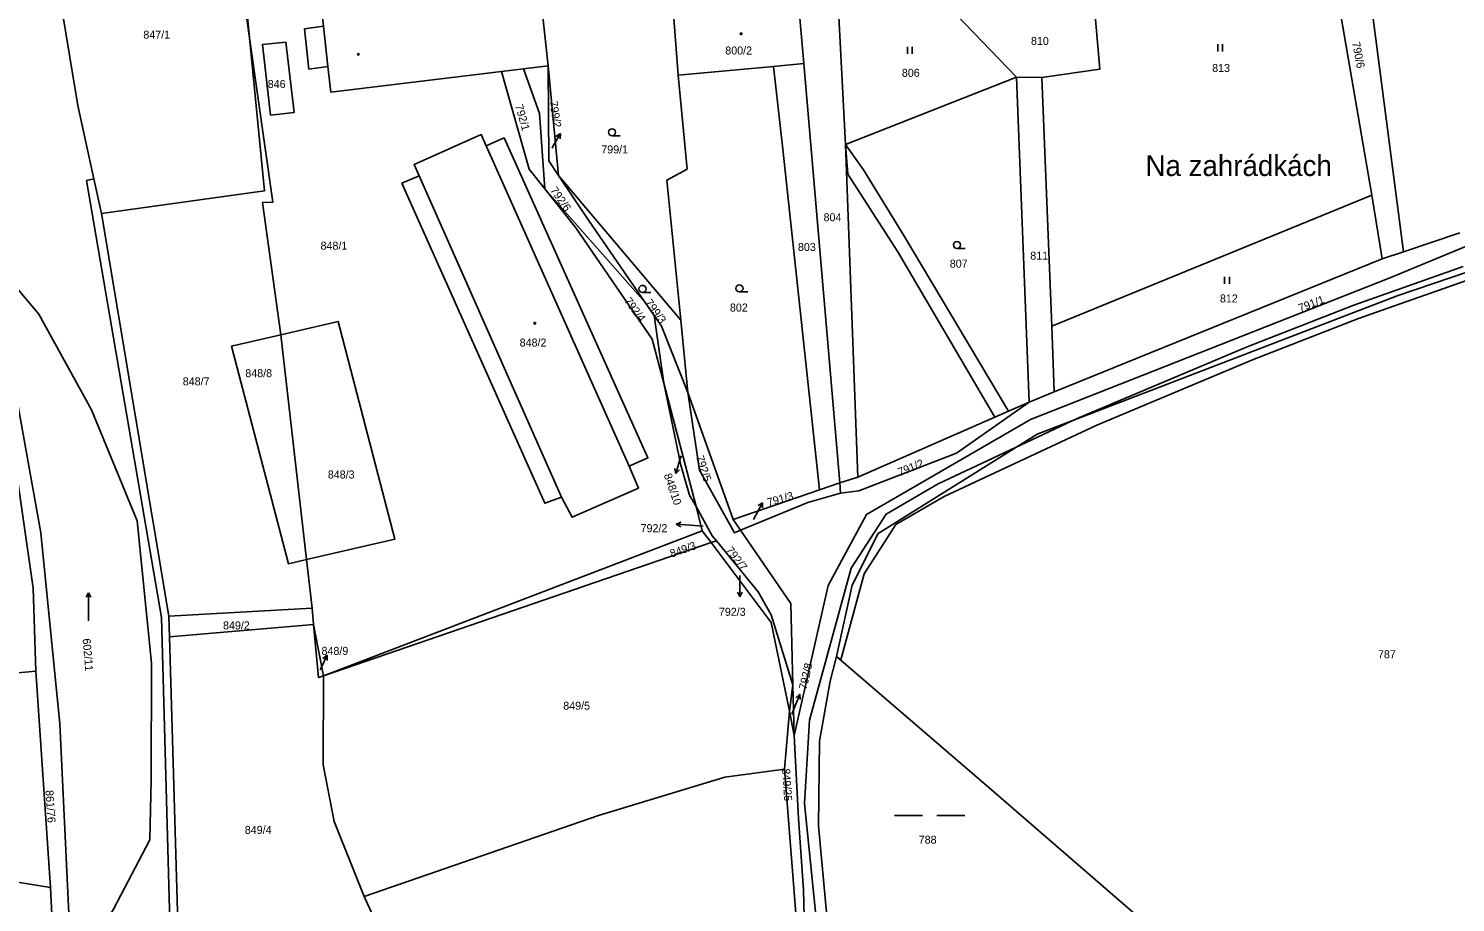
# Model space of a CAD drawing. Extents: x -757266 to -753360, y -1162585 to -1157740.
# Drawn here: x -756892.7 to -756589.6, y -1159563.7 to -1159378.1 of the extents above; entities that cross this region are included whole.
import ezdxf

# ---------------------------------------------------------------- set-up
doc = ezdxf.new("R2010")
doc.units = 0
for name, color, linetype in [('Hranice parcel', 7, 'Continuous'), ('Parcelní čísla', 7, 'Continuous'), ('Pop  PČ popisy', 7, 'Continuous'), ('Vnitřní kresba', 7, 'Continuous'), ('Věcná břemena k části', 7, 'Continuous'), ('Značky budov', 7, 'Continuous'), ('Značky kultur', 7, 'Continuous')]:
    doc.layers.add(name, color=color, linetype=linetype)

msp = doc.modelspace()

# ---------------------------------------------------------------- linework, layer by layer
at = {"layer": 'Hranice parcel'}
for p, q in [((-756719.18, -1159402.74), (-756720.72, -1159372.88)), ((-756682.81, -1159388.39), (-756699.51, -1159371.08)), ((-756782.33, -1159386), (-756783.53, -1159374.95)), ((-756734.47, -1159386.15), (-756727.97, -1159385.55)), ((-756720.33, -1159474.57), (-756727.97, -1159385.55)), ((-756792.21, -1159387.19), (-756787.55, -1159386.63)), ((-756787.55, -1159386.63), (-756782.33, -1159386)), ((-756782.33, -1159386), (-756780.14, -1159409.28)), ((-756754.68, -1159388), (-756734.47, -1159386.15)), ((-756719.18, -1159402.74), (-756682.81, -1159388.39)), ((-756680.1, -1159457.44), (-756682.81, -1159388.39)), ((-756682.81, -1159388.39), (-756677.42, -1159388.52)), ((-756675.34, -1159441.31), (-756677.42, -1159388.52)), ((-756716.5, -1159473.39), (-756719.18, -1159402.74)), ((-756780.14, -1159409.28), (-756754.16, -1159440.02)), ((-756877.23, -1159417.39), (-756878.84, -1159410.04)), ((-756761.71, -1159436.3), (-756783.04, -1159412.14)), ((-756607.32, -1159413.48), (-756675.34, -1159441.31)), ((-756605.14, -1159427.02), (-756607.32, -1159413.48)), ((-756862.88, -1159502.93), (-756877.23, -1159417.39)), ((-756600.59, -1159425.5), (-756588.6, -1159421.48)), ((-756674.79, -1159455.28), (-756605.14, -1159427.02)), ((-756605.14, -1159427.02), (-756600.59, -1159425.5)), ((-756759.8, -1159439.07), (-756761.71, -1159436.3)), ((-756757.74, -1159453.43), (-756759.8, -1159439.07)), ((-756754.16, -1159440.02), (-756752.65, -1159455.42)), ((-756839.14, -1159443.12), (-756833.66, -1159490.89)), ((-756674.79, -1159455.28), (-756675.34, -1159441.31)), ((-756757.74, -1159453.43), (-756750.9, -1159479.64)), ((-756752.65, -1159455.42), (-756743.03, -1159482.35)), ((-756680.1, -1159457.44), (-756674.79, -1159455.28)), ((-756720.33, -1159474.57), (-756716.5, -1159473.39)), ((-756743.03, -1159482.35), (-756724.65, -1159476.05)), ((-756724.65, -1159476.05), (-756720.33, -1159474.57)), ((-756720.33, -1159474.57), (-756720.2, -1159476.81)), ((-756749.57, -1159484.76), (-756750.9, -1159479.64)), ((-756743.03, -1159482.35), (-756741.45, -1159484.66)), ((-756749.57, -1159484.76), (-756830.03, -1159515.56)), ((-756747.67, -1159487.28), (-756749.57, -1159484.76)), ((-756830.03, -1159515.56), (-756747.67, -1159487.28)), ((-756747.67, -1159487.28), (-756746.55, -1159486.9)), ((-756833.66, -1159490.89), (-756832.47, -1159501.24)), ((-756832.47, -1159501.24), (-756862.88, -1159502.93)), ((-756862.76, -1159507.3), (-756862.88, -1159502.93)), ((-756832.14, -1159504.69), (-756832.47, -1159501.24)), ((-756862.76, -1159507.3), (-756832.14, -1159504.69)), ((-756830.03, -1159515.56), (-756832.14, -1159504.69)), ((-756860.32, -1159592.53), (-756862.76, -1159507.3)), ((-756909.6, -1159516.31), (-756891.18, -1159514.56)), ((-756888.08, -1159560.56), (-756891.18, -1159514.56)), ((-756730.32, -1159517.52), (-756731.05, -1159523.12)), ((-756730.02, -1159528.29), (-756730.32, -1159517.52)), ((-756732.09, -1159535.43), (-756731.05, -1159523.12)), ((-756731.05, -1159523.12), (-756730.02, -1159528.29)), ((-756728.56, -1159581), (-756732.09, -1159535.43)), ((-756924.26, -1159554.77), (-756888.08, -1159560.56)), ((-756886.84, -1159585.24), (-756888.08, -1159560.56)), ((-756809.73, -1159588.01), (-756821.38, -1159562.46))]:
    msp.add_line(p, q, dxfattribs=at)
for points in [[(-756836.08, -1159324.04), (-756834.39, -1159339.05), (-756830.04, -1159377.58), (-756829.16, -1159386.14), (-756828.46, -1159391.58), (-756792.21, -1159387.19)], [(-756617.96, -1159329.16), (-756613.19, -1159328.59), (-756600.59, -1159425.5)], [(-756607.32, -1159413.48), (-756614.2, -1159373.6), (-756617.96, -1159329.16)], [(-756882.88, -1159333.6), (-756868.52, -1159332.73), (-756848.31, -1159353.74), (-756845.75, -1159380.05)], [(-756845.75, -1159380.05), (-756849.31, -1159354.8), (-756871.83, -1159335.95), (-756891.14, -1159340.49)], [(-756878.84, -1159410.04), (-756882.25, -1159394.41), (-756891.14, -1159340.49)], [(-756755.93, -1159368.82), (-756755.45, -1159375.88), (-756755.64, -1159375.9), (-756754.68, -1159388)], [(-756677.42, -1159388.52), (-756665.13, -1159386.75), (-756666.76, -1159367.95)], [(-756727.97, -1159385.55), (-756729.06, -1159373.5), (-756728.59, -1159373.55)], [(-756877.23, -1159417.39), (-756842.59, -1159412.57), (-756845.75, -1159380.05)], [(-756845.75, -1159380.05), (-756840.83, -1159414.98), (-756843.03, -1159415.06), (-756839.14, -1159443.12)], [(-756838.02, -1159381), (-756842.99, -1159381.48), (-756841.28, -1159396.49), (-756836.3, -1159395.96), (-756838.02, -1159381)], [(-756783.04, -1159412.14), (-756786.33, -1159407.98), (-756792.21, -1159387.19)], [(-756783.04, -1159412.14), (-756784.18, -1159396.16), (-756787.55, -1159386.63)], [(-756782.33, -1159386), (-756782.19, -1159406.22), (-756780.14, -1159409.28)], [(-756754.68, -1159388), (-756752.8, -1159407.95), (-756757.07, -1159410.29), (-756754.16, -1159440.02)], [(-756724.65, -1159476.05), (-756732.47, -1159403.74), (-756734.47, -1159386.15)], [(-756813.44, -1159410.94), (-756782.99, -1159478.91), (-756779.46, -1159477.67), (-756777.21, -1159481.9), (-756763.13, -1159475.73), (-756765.12, -1159471.06), (-756761.14, -1159469.29), (-756791.66, -1159401.32), (-756795.5, -1159403.03), (-756796.58, -1159400.61), (-756810.8, -1159406.95), (-756809.73, -1159409.36), (-756813.44, -1159410.94)], [(-756518.53, -1159405.91), (-756566.06, -1159415.52), (-756603.63, -1159431.14), (-756679.86, -1159461.14), (-756714.68, -1159481.31), (-756722.84, -1159496.4), (-756730.02, -1159528.29)], [(-756780.14, -1159409.28), (-756773.63, -1159418.99), (-756761.71, -1159436.3)], [(-756878.84, -1159410.04), (-756880.4, -1159410.39), (-756864.45, -1159503.19), (-756861.05, -1159627.24), (-756861.08, -1159653.69), (-756855.08, -1159693.86), (-756853.1, -1159698.91)], [(-756783.04, -1159412.14), (-756776.47, -1159420.45), (-756760.19, -1159444.04), (-756757.74, -1159453.43)], [(-756528.91, -1159414.06), (-756563.38, -1159421.74), (-756601.97, -1159434.88), (-756678.44, -1159464.24), (-756712.18, -1159485.32), (-756717.75, -1159496.31), (-756721.03, -1159511.46)], [(-756900.5, -1159427.51), (-756898.83, -1159429.01), (-756890.5, -1159438.79), (-756879.34, -1159459.1), (-756869.66, -1159482.64), (-756866.57, -1159512.91), (-756866.68, -1159537.66), (-756866.93, -1159550.4), (-756874.67, -1159565.14), (-756883.49, -1159579.55)], [(-756900.5, -1159427.51), (-756890.08, -1159485.19), (-756886.05, -1159525.8), (-756883.49, -1159579.55)], [(-756759.8, -1159439.07), (-756758.26, -1159441.32), (-756752.65, -1159455.42)], [(-756839.14, -1159443.12), (-756849.57, -1159445.53), (-756837.5, -1159491.78), (-756833.66, -1159490.89)], [(-756833.66, -1159490.89), (-756814.88, -1159486.56), (-756826.95, -1159440.31), (-756839.14, -1159443.12)], [(-756750.9, -1159479.64), (-756752.26, -1159477.19), (-756754.16, -1159470.84), (-756757.74, -1159453.43)], [(-756752.65, -1159455.42), (-756750.17, -1159471.92), (-756742.74, -1159485.19), (-756741.45, -1159484.66)], [(-756680.1, -1159457.44), (-756695.58, -1159468.27), (-756716.3, -1159476.28), (-756720.2, -1159476.81)], [(-756716.5, -1159473.39), (-756687.42, -1159460.65), (-756684.49, -1159459.36), (-756680.1, -1159457.44)], [(-756891.18, -1159514.56), (-756891.71, -1159496.94), (-756896.42, -1159464.4)], [(-756746.55, -1159486.9), (-756747.47, -1159485.86), (-756750.9, -1159479.64)], [(-756720.2, -1159476.81), (-756727.15, -1159478.74), (-756741.45, -1159484.66)], [(-756741.45, -1159484.66), (-756730.79, -1159500.23), (-756730.32, -1159517.52)], [(-756747.67, -1159487.28), (-756734.93, -1159504.24), (-756731.05, -1159523.12)], [(-756730.32, -1159517.52), (-756734.97, -1159502.66), (-756737.73, -1159497.74), (-756746.55, -1159486.9)], [(-756832.14, -1159504.69), (-756831.08, -1159515.96), (-756830.03, -1159515.56)], [(-756721.03, -1159511.46), (-756722.4, -1159516.74), (-756724.7, -1159529.43), (-756724.87, -1159547.42), (-756723.02, -1159567.31)], [(-756721.03, -1159511.46), (-756688.71, -1159539.34), (-756653.94, -1159569.39), (-756651.67, -1159571.35)], [(-756821.38, -1159562.46), (-756827.77, -1159546.53), (-756830.12, -1159534.52), (-756830.03, -1159515.56)], [(-756730.02, -1159528.29), (-756729.15, -1159545.86), (-756728.07, -1159561.05), (-756727.24, -1159595.66), (-756727.85, -1159612.75), (-756728.58, -1159632.24), (-756729.69, -1159654.04)], [(-756821.38, -1159562.46), (-756771.64, -1159545.22), (-756744.75, -1159537.13), (-756732.09, -1159535.43)]]:
    msp.add_lwpolyline(points, dxfattribs=at)
at = {"layer": 'Pop  PČ popisy'}
for p, q in [((-756781.22, -1159403), (-756779.72, -1159400.401)), ((-756779.72, -1159400.401), (-756780.654, -1159401.018)), ((-756779.72, -1159400.401), (-756779.787, -1159401.519)), ((-756781.5, -1159403.49), (-756781.22, -1159403)), ((-756754.34, -1159469.74), (-756755.167, -1159472.625)), ((-756754.08, -1159468.87), (-756754.34, -1159469.74)), ((-756755.167, -1159472.625), (-756755.372, -1159471.524)), ((-756755.167, -1159472.625), (-756754.41, -1159471.8)), ((-756738.21, -1159481.43), (-756736.755, -1159478.805)), ((-756736.755, -1159478.805), (-756737.679, -1159479.438)), ((-756736.755, -1159478.805), (-756736.803, -1159479.924)), ((-756738.72, -1159482.36), (-756738.21, -1159481.43)), ((-756755.104, -1159483.361), (-756754.07, -1159482.931)), ((-756752.11, -1159483.57), (-756755.104, -1159483.361)), ((-756755.104, -1159483.361), (-756754.14, -1159483.93)), ((-756749.36, -1159483.78), (-756752.11, -1159483.57)), ((-756741.61, -1159494.29), (-756741.61, -1159495.78)), ((-756741.61, -1159498.781), (-756742.111, -1159497.78)), ((-756741.61, -1159495.78), (-756741.61, -1159498.781)), ((-756741.61, -1159498.781), (-756741.109, -1159497.78)), ((-756830.56, -1159513.9), (-756829.292, -1159511.18)), ((-756829.292, -1159511.18), (-756830.169, -1159511.876)), ((-756829.292, -1159511.18), (-756829.261, -1159512.299)), ((-756830.77, -1159514.34), (-756830.56, -1159513.9)), ((-756729.97, -1159522.29), (-756728.846, -1159519.508)), ((-756728.846, -1159519.508), (-756729.685, -1159520.248)), ((-756728.846, -1159519.508), (-756728.757, -1159520.624)), ((-756730.55, -1159523.71), (-756729.97, -1159522.29))]:
    msp.add_line(p, q, dxfattribs=at)
at = {"layer": 'Vnitřní kresba'}
for p, q in [((-756830.04, -1159377.58), (-756834.09, -1159378.13)), ((-756834.09, -1159378.13), (-756833.16, -1159386.73)), ((-756833.16, -1159386.73), (-756829.16, -1159386.14)), ((-756795.5, -1159403.03), (-756765.12, -1159471.06)), ((-756719.18, -1159402.74), (-756715.3, -1159408.14)), ((-756718.63, -1159409.03), (-756719.18, -1159402.74)), ((-756779.46, -1159477.67), (-756809.73, -1159409.36)), ((-756708.02, -1159425.55), (-756718.63, -1159409.03)), ((-756715.3, -1159408.14), (-756706.74, -1159422.05)), ((-756706.74, -1159422.05), (-756684.49, -1159459.36)), ((-756687.42, -1159460.65), (-756708.02, -1159425.55))]:
    msp.add_line(p, q, dxfattribs=at)
at = {"layer": 'Věcná břemena k části'}
for points in [[(-756587.89, -1159428.67), (-756611.13, -1159436.88), (-756633.78, -1159445.67), (-756669.9, -1159460.96), (-756683.01, -1159467.09), (-756699.49, -1159474.82), (-756710.54, -1159481.22), (-756717.96, -1159492.75), (-756726.79, -1159524.98), (-756727.87, -1159542.7)], [(-756723.02, -1159567.31), (-756724.87, -1159547.42), (-756724.7, -1159529.43), (-756722.4, -1159516.74), (-756721.03, -1159511.46), (-756720.17, -1159512.2), (-756715.18, -1159493.95), (-756708.42, -1159483.46), (-756698.17, -1159477.5), (-756665.72, -1159462.32), (-756632.68, -1159448.46), (-756610.13, -1159439.7), (-756586.97, -1159431.52)], [(-756727.87, -1159542.7), (-756723.85, -1159582.52)]]:
    msp.add_lwpolyline(points, dxfattribs=at)
at = {"layer": 'Značky budov'}
for centre in [(-756741.3268, -1159379.2092), (-756822.6468, -1159383.5792), (-756785.1568, -1159440.6892)]:
    msp.add_circle(centre, 0.175, dxfattribs=at)
at = {"layer": 'Značky kultur'}
for p, q in [((-756705.961, -1159383.5), (-756705.961, -1159382)), ((-756704.96, -1159383.5), (-756704.96, -1159382)), ((-756640.071, -1159382.94), (-756640.071, -1159381.44)), ((-756639.07, -1159382.94), (-756639.07, -1159381.44)), ((-756768.743, -1159400.88), (-756766.993, -1159400.88)), ((-756695.463, -1159424.83), (-756693.713, -1159424.83)), ((-756638.591, -1159432.34), (-756638.591, -1159430.84)), ((-756637.59, -1159432.34), (-756637.59, -1159430.84)), ((-756762.273, -1159434.15), (-756760.523, -1159434.15)), ((-756741.673, -1159434.04), (-756739.923, -1159434.04)), ((-756879.981, -1159497.933), (-756880.483, -1159498.91)), ((-756879.981, -1159503.933), (-756879.981, -1159497.933)), ((-756879.981, -1159497.933), (-756879.48, -1159498.91)), ((-756708.769, -1159545.27), (-756702.769, -1159545.27)), ((-756699.769, -1159545.27), (-756693.769, -1159545.27))]:
    msp.add_line(p, q, dxfattribs=at)
for centre in [(-756768.7429, -1159400.1298), (-756695.4629, -1159424.0798), (-756762.2729, -1159433.3998), (-756741.6729, -1159433.2898)]:
    msp.add_circle(centre, 0.75, dxfattribs=at)

# ---------------------------------------------------------------- texts
at = {"layer": 'Parcelní čísla'}
for s, p in [('847/1', (-756868.33, -1159380.25)), ('800/2', (-756744.69, -1159383.61)), ('810', (-756679.74, -1159381.57)), ('813', (-756641.25, -1159387.32)), ('806', (-756707.17, -1159388.35)), ('846', (-756841.895, -1159390.72)), ('799/1', (-756771.03, -1159404.62)), ('804', (-756723.8, -1159419.03)), ('848/1', (-756830.67, -1159425.07)), ('803', (-756729.25, -1159425.34)), ('807', (-756696.99, -1159428.88)), ('811', (-756679.89, -1159427.19)), ('802', (-756743.7, -1159438.21)), ('812', (-756639.6, -1159436.28)), ('848/2', (-756788.37, -1159445.64)), ('848/7', (-756859.95, -1159453.89)), ('848/8', (-756846.66, -1159452.15)), ('848/3', (-756829.13, -1159473.67)), ('792/2', (-756762.677, -1159485.07)), ('792/3', (-756746.047, -1159502.838)), ('849/2', (-756851.4, -1159505.73)), ('848/9', (-756830.47, -1159511.13)), ('787', (-756606.02, -1159511.85)), ('849/5', (-756779.11, -1159522.78)), ('849/4', (-756846.77, -1159549.16)), ('788', (-756703.6, -1159551.24))]:
    msp.add_text(s, height=1.7, dxfattribs=at).set_placement(p)
for s, rotation, p in [('790/6', 281, (-756611.544, -1159381.062)), ('792/1', 286, (-756789.367, -1159394.484)), ('799/2', 279, (-756782.049, -1159393.622)), ('792/6', 305, (-756781.966, -1159412.457)), ('792/4', 306, (-756766.217, -1159435.969)), ('799/3', 306, (-756761.817, -1159436.329)), ('791/1', 21, (-756622.535, -1159438.353)), ('792/5', 288, (-756750.948, -1159469.112)), ('791/2', 21.999997, (-756707.621, -1159473.198)), ('848/10', 289, (-756757.774, -1159472.912)), ('791/3', 16, (-756735.525, -1159479.617)), ('849/3', 19, (-756756.093, -1159490.483)), ('792/7', 307, (-756744.638, -1159488.901)), ('602/11', 275, (-756881.246, -1159507.724)), ('792/8', 77, (-756727.431, -1159518.631)), ('849/25', 274, (-756732.637, -1159535.339)), ('861/76', 274, (-756889.127, -1159539.919))]:
    msp.add_text(s, height=1.7, rotation=rotation, dxfattribs=at).set_placement(p)
at = {"layer": 'Pop  PČ popisy'}
msp.add_text('Na zahrádkách', height=4.399998, dxfattribs=at).set_placement((-756655.4, -1159409.41))

doc.saveas('drawing.dxf')
